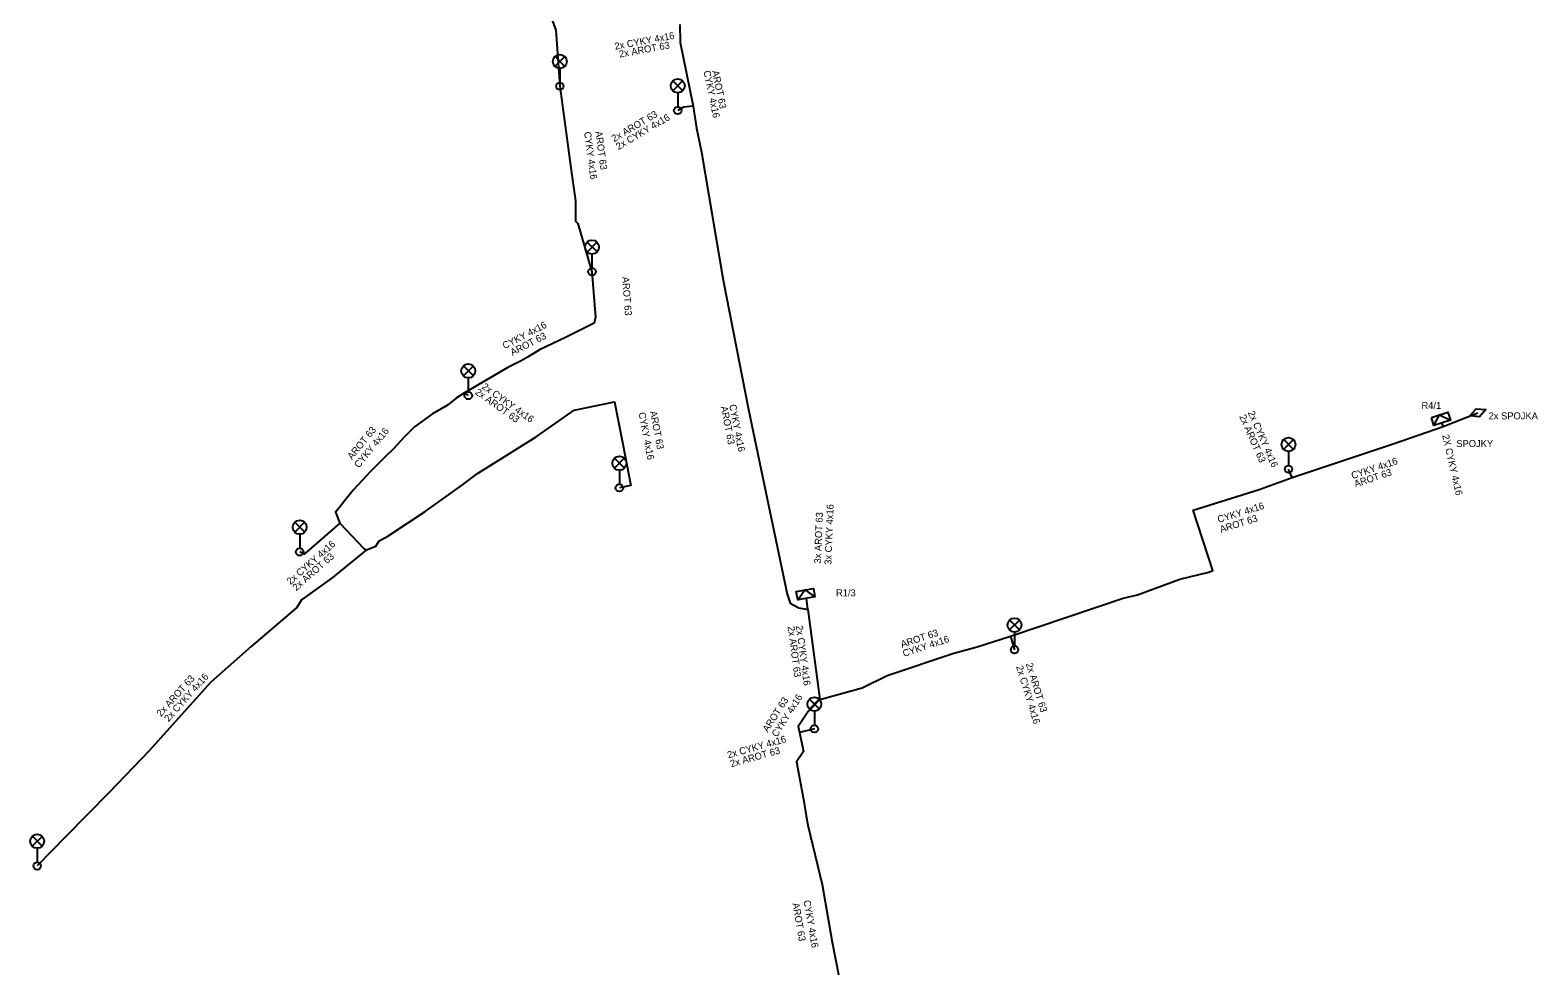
# Model space of a CAD drawing. Extents: x -641884 to -641258, y -1196509 to -1195931.
# Drawn here: x -641878.2 to -641716.2, y -1196225.6 to -1196125 of the extents above; entities that cross this region are included whole.
import ezdxf

# ---------------------------------------------------------------- set-up
doc = ezdxf.new("R2010")
doc.units = 0
for name, color, linetype in [('CIZÍ_NADZEM', 7, 'Continuous'), ('CIZÍ_NADZEM_POPIS', 7, 'Continuous'), ('DOPLŇ_POPISY', 7, 'Continuous'), ('TECH_OCHR_PÁSMO_HRAN', 7, 'Continuous'), ('Vrstva 20', 7, 'Continuous'), ('Vrstva 22', 7, 'Continuous'), ('Vrstva 31', 7, 'Continuous'), ('Vrstva 8', 7, 'Continuous'), ('ZP_EON', 7, 'Continuous'), ('ZP_EON_POPIS', 7, 'Continuous')]:
    doc.layers.add(name, color=color, linetype=linetype)

msp = doc.modelspace()

# ---------------------------------------------------------------- linework, layer by layer
at = {"layer": 'CIZÍ_NADZEM'}
for points in [[(-641727.67, -1196166.65), (-641725.89, -1196166.08), (-641725.61, -1196166.93), (-641727.39, -1196167.51)], [(-641795.91, -1196185.36), (-641794.06, -1196185.03), (-641793.91, -1196185.92), (-641795.75, -1196186.24)]]:
    msp.add_lwpolyline(points, close=True, dxfattribs=at)
for points in [[(-641727.39, -1196167.51), (-641726.78, -1196166.36), (-641725.61, -1196166.93)], [(-641795.75, -1196186.24), (-641794.99, -1196185.19), (-641793.91, -1196185.92)]]:
    msp.add_lwpolyline(points, dxfattribs=at)
at = {"layer": 'DOPLŇ_POPISY'}
msp.add_lwpolyline([(-641723.55, -1196166.49), (-641722.85, -1196165.71), (-641721.81, -1196165.81), (-641722.51, -1196166.59)], close=True, dxfattribs=at)
at = {"layer": 'TECH_OCHR_PÁSMO_HRAN'}
for p, q in [((-641831.56, -1196164.01), (-641831.15, -1196164.3)), ((-641742.62, -1196173.12), (-641743.02, -1196172.21)), ((-641794.66, -1196187.28), (-641794.83, -1196186.08)), ((-641794.66, -1196187.28), (-641793.37, -1196196.96)), ((-641772.91, -1196190.14), (-641772.46, -1196191.61)), ((-641793.97, -1196200.12), (-641795.57, -1196200.51))]:
    msp.add_line(p, q, dxfattribs=at)
for points in [[(-641830.01, -1196117), (-641829.85, -1196118.45), (-641827.11, -1196119.55), (-641826.03, -1196119.67), (-641825.6, -1196119.67), (-641824.9, -1196119.96), (-641824.15, -1196120.83), (-641823.46, -1196121.63), (-641822.6, -1196122.69), (-641821.76, -1196125.04), (-641821.32, -1196131.05)], [(-641808.42, -1196124.41), (-641808.4, -1196126.35), (-641806.98, -1196133.21)], [(-641821.32, -1196131.05), (-641820.06, -1196140.36), (-641819.64, -1196143.38), (-641819.62, -1196145.55), (-641819.39, -1196145.8), (-641817.86, -1196150.99)], [(-641806.98, -1196133.21), (-641808.04, -1196133.3), (-641808.65, -1196133.66)], [(-641806.98, -1196133.21), (-641806.64, -1196135.57), (-641806.11, -1196138.14), (-641803.76, -1196151.9), (-641801.05, -1196165.8), (-641798.91, -1196176.06), (-641796.9, -1196185.64), (-641796.57, -1196186.6), (-641795.65, -1196187.11), (-641794.66, -1196187.28)], [(-641817.86, -1196150.99), (-641817.5, -1196155.87), (-641817.62, -1196156.51), (-641820.62, -1196158.01), (-641823.49, -1196159.38), (-641824.71, -1196160.15), (-641825.48, -1196160.56), (-641826.89, -1196161.29), (-641831.56, -1196164.01)], [(-641817.86, -1196150.99), (-641817.5, -1196155.87), (-641817.62, -1196156.51)], [(-641831.56, -1196164.01), (-641832.44, -1196164.58), (-641833.39, -1196165.33), (-641835, -1196166.26), (-641836.95, -1196167.64), (-641837.99, -1196168.72), (-641839.24, -1196170.04), (-641840, -1196170.81), (-641841.68, -1196172.49), (-641843.48, -1196174.44), (-641844.28, -1196175.41), (-641845.01, -1196176.35), (-641845.41, -1196176.82), (-641844.97, -1196178)], [(-641844.97, -1196178), (-641842.36, -1196180.73), (-641842.1, -1196180.88), (-641841.1, -1196180.48), (-641840.72, -1196179.91), (-641839.8, -1196179.4), (-641835.77, -1196176.76), (-641831.76, -1196173.88), (-641830.16, -1196172.66), (-641823.87, -1196168.73), (-641819.76, -1196165.87), (-641815.44, -1196164.96), (-641814.56, -1196169.52), (-641813.67, -1196173.97), (-641814.92, -1196174.22)], [(-641742.62, -1196173.12), (-641731.79, -1196169.5), (-641726.41, -1196167.61), (-641722.68, -1196166.15)], [(-641772.91, -1196190.14), (-641760.78, -1196186.07), (-641759.25, -1196185.72), (-641754.7, -1196184.02), (-641751.57, -1196183.29), (-641751.16, -1196183.08), (-641753.27, -1196176.6), (-641746.19, -1196174.4), (-641742.62, -1196173.12)], [(-641844.97, -1196178), (-641848.77, -1196181.34), (-641849.27, -1196181.1)], [(-641842.1, -1196180.88), (-641845.79, -1196183.9), (-641849.09, -1196186.24), (-641849.59, -1196187.06), (-641854.47, -1196191.27), (-641858.84, -1196195.13), (-641865.43, -1196202.47), (-641869.74, -1196206.95), (-641874.42, -1196211.73), (-641877.48, -1196214.85)], [(-641793.37, -1196196.96), (-641788.83, -1196195.7), (-641786.13, -1196194.37), (-641778.97, -1196191.99), (-641776.49, -1196191.3), (-641772.91, -1196190.14)], [(-641793.37, -1196196.96), (-641794.65, -1196198.24), (-641795.7, -1196199.88), (-641795.57, -1196200.51)], [(-641795.57, -1196200.51), (-641795.14, -1196202.56), (-641795.9, -1196203.65), (-641795.08, -1196208.11), (-641794.86, -1196209.45), (-641794.67, -1196210.46), (-641793.14, -1196216.85), (-641792.05, -1196223.04), (-641790.98, -1196228.54), (-641790.42, -1196231.44)]]:
    msp.add_lwpolyline(points, dxfattribs=at)
at = {"layer": 'Vrstva 31'}
for p, q in [((-641821.85, -1196128.93), (-641820.79, -1196127.87)), ((-641820.78, -1196128.92), (-641821.83, -1196127.86)), ((-641821.32, -1196129.15), (-641821.32, -1196130.65)), ((-641809.18, -1196131.54), (-641808.12, -1196130.48)), ((-641808.11, -1196131.53), (-641809.16, -1196130.47)), ((-641808.65, -1196131.76), (-641808.65, -1196133.26)), ((-641818.39, -1196148.87), (-641817.33, -1196147.81)), ((-641817.32, -1196148.86), (-641818.37, -1196147.8)), ((-641817.86, -1196149.09), (-641817.86, -1196150.59)), ((-641831.68, -1196162.18), (-641830.62, -1196161.12)), ((-641830.61, -1196162.17), (-641831.66, -1196161.11)), ((-641831.15, -1196162.4), (-641831.15, -1196163.9)), ((-641743.55, -1196170.09), (-641742.49, -1196169.03)), ((-641742.48, -1196170.08), (-641743.53, -1196169.02)), ((-641815.45, -1196172.1), (-641814.39, -1196171.04)), ((-641814.38, -1196172.09), (-641815.43, -1196171.03)), ((-641743.02, -1196170.31), (-641743.02, -1196171.81)), ((-641814.92, -1196172.32), (-641814.92, -1196173.82)), ((-641849.8, -1196178.98), (-641848.74, -1196177.92)), ((-641848.73, -1196178.97), (-641849.78, -1196177.91)), ((-641849.27, -1196179.2), (-641849.27, -1196180.7)), ((-641772.99, -1196189.49), (-641771.93, -1196188.43)), ((-641771.92, -1196189.48), (-641772.97, -1196188.42)), ((-641772.46, -1196189.71), (-641772.46, -1196191.21)), ((-641794.5, -1196198), (-641793.44, -1196196.94)), ((-641793.43, -1196197.99), (-641794.48, -1196196.93)), ((-641793.97, -1196198.22), (-641793.97, -1196199.72)), ((-641878.01, -1196212.73), (-641876.95, -1196211.67)), ((-641876.94, -1196212.72), (-641877.99, -1196211.66)), ((-641877.48, -1196212.95), (-641877.48, -1196214.45))]:
    msp.add_line(p, q, dxfattribs=at)
for centre, radius in [((-641821.32, -1196128.4), 0.75), ((-641821.32, -1196131.05), 0.4), ((-641808.65, -1196131.01), 0.75), ((-641808.65, -1196133.66), 0.4), ((-641817.86, -1196148.34), 0.75), ((-641817.86, -1196150.99), 0.4), ((-641831.15, -1196161.65), 0.75), ((-641831.15, -1196164.3), 0.4), ((-641743.02, -1196169.56), 0.75), ((-641814.92, -1196171.57), 0.75), ((-641743.02, -1196172.21), 0.4), ((-641814.92, -1196174.22), 0.4), ((-641849.27, -1196178.45), 0.75), ((-641849.27, -1196181.1), 0.4), ((-641772.46, -1196188.96), 0.75), ((-641772.46, -1196191.61), 0.4), ((-641793.97, -1196197.47), 0.75), ((-641793.97, -1196200.12), 0.4), ((-641877.48, -1196212.2), 0.75), ((-641877.48, -1196214.85), 0.4)]:
    msp.add_circle(centre, radius, dxfattribs=at)
at = {"layer": 'ZP_EON'}
for p, q in [((-641831.56, -1196164.01), (-641831.15, -1196164.3)), ((-641726.41, -1196167.61), (-641722.68, -1196166.15)), ((-641726.41, -1196167.61), (-641726.5, -1196167.22)), ((-641742.62, -1196173.12), (-641743.02, -1196172.21)), ((-641794.66, -1196187.28), (-641794.83, -1196186.08)), ((-641794.66, -1196187.28), (-641793.37, -1196196.96)), ((-641772.91, -1196190.14), (-641772.46, -1196191.61)), ((-641793.97, -1196200.12), (-641795.57, -1196200.51))]:
    msp.add_line(p, q, dxfattribs=at)
for points in [[(-641830.01, -1196117), (-641829.85, -1196118.45), (-641827.11, -1196119.55), (-641826.03, -1196119.67), (-641825.6, -1196119.67), (-641824.9, -1196119.96), (-641824.15, -1196120.83), (-641823.46, -1196121.63), (-641822.6, -1196122.69), (-641821.76, -1196125.04), (-641821.32, -1196131.05)], [(-641808.42, -1196124.41), (-641808.4, -1196126.35), (-641806.98, -1196133.21)], [(-641821.32, -1196131.05), (-641820.06, -1196140.36), (-641819.64, -1196143.38), (-641819.62, -1196145.55), (-641819.39, -1196145.8), (-641817.86, -1196150.99)], [(-641806.98, -1196133.21), (-641808.04, -1196133.3), (-641808.65, -1196133.66)], [(-641806.98, -1196133.21), (-641806.64, -1196135.57), (-641806.11, -1196138.14), (-641803.76, -1196151.9), (-641801.05, -1196165.8), (-641798.91, -1196176.06), (-641796.9, -1196185.64), (-641796.57, -1196186.6), (-641795.65, -1196187.11), (-641794.66, -1196187.28)], [(-641817.86, -1196150.99), (-641817.5, -1196155.87), (-641817.62, -1196156.51), (-641820.62, -1196158.01), (-641823.49, -1196159.38), (-641824.71, -1196160.15), (-641825.48, -1196160.56), (-641826.89, -1196161.29), (-641831.56, -1196164.01)], [(-641831.56, -1196164.01), (-641832.44, -1196164.58), (-641833.39, -1196165.33), (-641835, -1196166.26), (-641836.95, -1196167.64), (-641837.99, -1196168.72), (-641839.24, -1196170.04), (-641840, -1196170.81), (-641841.68, -1196172.49), (-641843.48, -1196174.44), (-641844.28, -1196175.41), (-641845.01, -1196176.35), (-641845.41, -1196176.82), (-641844.97, -1196178)], [(-641844.97, -1196178), (-641842.36, -1196180.73), (-641842.1, -1196180.88), (-641841.1, -1196180.48), (-641840.72, -1196179.91), (-641839.8, -1196179.4), (-641835.77, -1196176.76), (-641831.76, -1196173.88), (-641830.16, -1196172.66), (-641823.87, -1196168.73), (-641819.76, -1196165.87), (-641815.44, -1196164.96), (-641814.56, -1196169.52), (-641813.67, -1196173.97), (-641814.92, -1196174.22)], [(-641742.62, -1196173.12), (-641731.79, -1196169.5), (-641726.41, -1196167.61)], [(-641772.91, -1196190.14), (-641760.78, -1196186.07), (-641759.25, -1196185.72), (-641754.7, -1196184.02), (-641751.57, -1196183.29), (-641751.16, -1196183.08), (-641753.27, -1196176.6), (-641746.19, -1196174.4), (-641742.62, -1196173.12)], [(-641844.97, -1196178), (-641848.77, -1196181.34), (-641849.27, -1196181.1)], [(-641842.1, -1196180.88), (-641845.79, -1196183.9), (-641849.09, -1196186.24), (-641849.59, -1196187.06), (-641854.47, -1196191.27), (-641858.84, -1196195.13), (-641865.43, -1196202.47), (-641869.74, -1196206.95), (-641874.42, -1196211.73), (-641877.48, -1196214.85)], [(-641793.37, -1196196.96), (-641788.83, -1196195.7), (-641786.13, -1196194.37), (-641778.97, -1196191.99), (-641776.49, -1196191.3), (-641772.91, -1196190.14)], [(-641793.37, -1196196.96), (-641794.65, -1196198.24), (-641795.7, -1196199.88), (-641795.57, -1196200.51)], [(-641795.57, -1196200.51), (-641795.14, -1196202.56), (-641795.9, -1196203.65), (-641795.08, -1196208.11), (-641794.86, -1196209.45), (-641794.67, -1196210.46), (-641793.14, -1196216.85), (-641792.05, -1196223.04), (-641790.98, -1196228.54), (-641790.42, -1196231.44)]]:
    msp.add_lwpolyline(points, dxfattribs=at)

# ---------------------------------------------------------------- texts
at = {"layer": 'CIZÍ_NADZEM_POPIS'}
for s, p in [('R4/1', (-641728.73, -1196165.73)), ('R1/3', (-641791.64, -1196185.87))]:
    msp.add_text(s, height=0.75, dxfattribs=at).set_placement(p)
at = {"layer": 'Vrstva 20'}
msp.add_text('SPOJKY', height=0.75, dxfattribs=at).set_placement((-641724.99, -1196169.83))
at = {"layer": 'Vrstva 22'}
for s, rotation, p in [('2x AROT 63', 10.5278, (-641814.88, -1196127.98)), ('AROT 63', 281.6949, (-641804.97, -1196129.43)), ('2x AROT 63', 30.5476, (-641815.49, -1196137.07)), ('AROT 63', 277.7075, (-641817.51, -1196135.93)), ('AROT 63', 274.2191, (-641814.62, -1196151.56)), ('AROT 63', 27.372, (-641826.4, -1196160.04)), ('2x AROT 63', 324.7276, (-641830.5, -1196164.08)), ('AROT 63', 280.9228, (-641811.64, -1196166.03)), ('AROT 63', 281.0322, (-641804.03, -1196165.51)), ('2x AROT 63', 293.7284, (-641748.33, -1196166.54)), ('AROT 63', 50.4862, (-641843.65, -1196171.24)), ('AROT 63', 18.4825, (-641735.82, -1196174.17)), ('3x AROT 63', 87.7536, (-641793.26, -1196182.36)), ('AROT 63', 17.2618, (-641750.27, -1196179.04)), ('2x AROT 63', 41.3138, (-641849.64, -1196185.34)), ('2x AROT 63', 277.5908, (-641796.84, -1196189.13)), ('AROT 63', 18.3869, (-641784.55, -1196191.41)), ('2x AROT 63', 287.0205, (-641771.25, -1196193.14)), ('2x AROT 63', 48.0819, (-641864.17, -1196198.86)), ('AROT 63', 57.3708, (-641798.97, -1196200.54)), ('2x AROT 63', 15.7445, (-641802.9, -1196204.25)), ('AROT 63', 279.9869, (-641796.34, -1196218.88))]:
    msp.add_text(s, height=0.75, rotation=rotation, dxfattribs=at).set_placement(p)
at = {"layer": 'Vrstva 8'}
msp.add_text('2x SPOJKA', height=0.75, dxfattribs=at).set_placement((-641721.52, -1196166.85))
at = {"layer": 'ZP_EON_POPIS'}
for s, rotation, p in [('2x CYKY 4x16', 10.5278, (-641815.36, -1196127.14)), ('CYKY 4x16', 281.6949, (-641805.89, -1196129.44)), ('2x CYKY 4x16', 30.5476, (-641815.02, -1196137.93)), ('CYKY 4x16', 277.7075, (-641818.72, -1196135.98)), ('CYKY 4x16', 27.372, (-641827.25, -1196159.33)), ('2x CYKY 4x16', 324.7276, (-641829.77, -1196163.49)), ('CYKY 4x16', 280.9228, (-641812.87, -1196166.17)), ('CYKY 4x16', 281.0322, (-641803.12, -1196165.31)), ('2x CYKY 4x16', 293.7284, (-641747.41, -1196166.13)), ('CYKY 4x16', 50.4862, (-641842.91, -1196172.14)), ('2X CYKY 4x16', 282.9946, (-641726.52, -1196168.57)), ('CYKY 4x16', 18.4825, (-641736.14, -1196173.28)), ('3x CYKY 4x16', 87.7536, (-641792.14, -1196182.5)), ('CYKY 4x16', 17.2618, (-641750.52, -1196177.99)), ('2x CYKY 4x16', 41.3138, (-641850.26, -1196184.67)), ('2x CYKY 4x16', 277.5908, (-641795.96, -1196189.04)), ('CYKY 4x16', 18.3869, (-641784.33, -1196192.4)), ('2x CYKY 4x16', 48.0819, (-641863.36, -1196199.41)), ('2x CYKY 4x16', 287.0205, (-641772.3, -1196193.43)), ('CYKY 4x16', 57.3708, (-641797.99, -1196201.07)), ('2x CYKY 4x16', 15.7445, (-641803.21, -1196203.3)), ('CYKY 4x16', 279.9869, (-641795.14, -1196218.59))]:
    msp.add_text(s, height=0.75, rotation=rotation, dxfattribs=at).set_placement(p)

doc.saveas('drawing.dxf')
